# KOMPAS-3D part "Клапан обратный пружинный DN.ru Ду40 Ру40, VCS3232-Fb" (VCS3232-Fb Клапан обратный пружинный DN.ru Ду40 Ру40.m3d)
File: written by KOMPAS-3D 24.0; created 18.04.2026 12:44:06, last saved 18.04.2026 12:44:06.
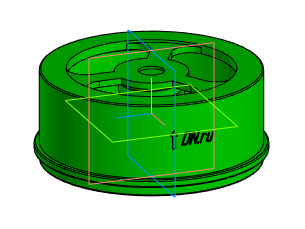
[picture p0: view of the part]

Document properties: Автор: 712; Полное имя файла: C:\Users\712\Desktop\Новая папка (4)\VCS3232-Fb Клапан обратный пружинный DN.ru Ду40 Ру40.m3d

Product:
- Body: Тело 1  | qty 1
    Масса: 0.509779
- Part/product: Клапан обратный пружинный DN.ru Ду40 Ру40  | designation VCS3232-Fb
    Масса: 0.61
    Раздел спецификации: Прочие изделия
    Примечание: D100-03890
    additional columns: 071bd168-1a06-425c-849c-e99e84a96128; Деталь; 712; c; Шероховатость не задана; Да

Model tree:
1. Операция без истории:2

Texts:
  VCS3232-Fb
